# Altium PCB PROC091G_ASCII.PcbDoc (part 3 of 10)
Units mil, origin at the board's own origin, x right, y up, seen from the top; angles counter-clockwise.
Board outline 4538.11 x 994.94 mil, 8 copper layers (Top Layer, GND1, Sig1, PWR1, PWR2, Sig2, GND2, Bottom Layer), stack 59.155 mil thick; 447 components, 329 nets, 5050 pads, 868 vias.
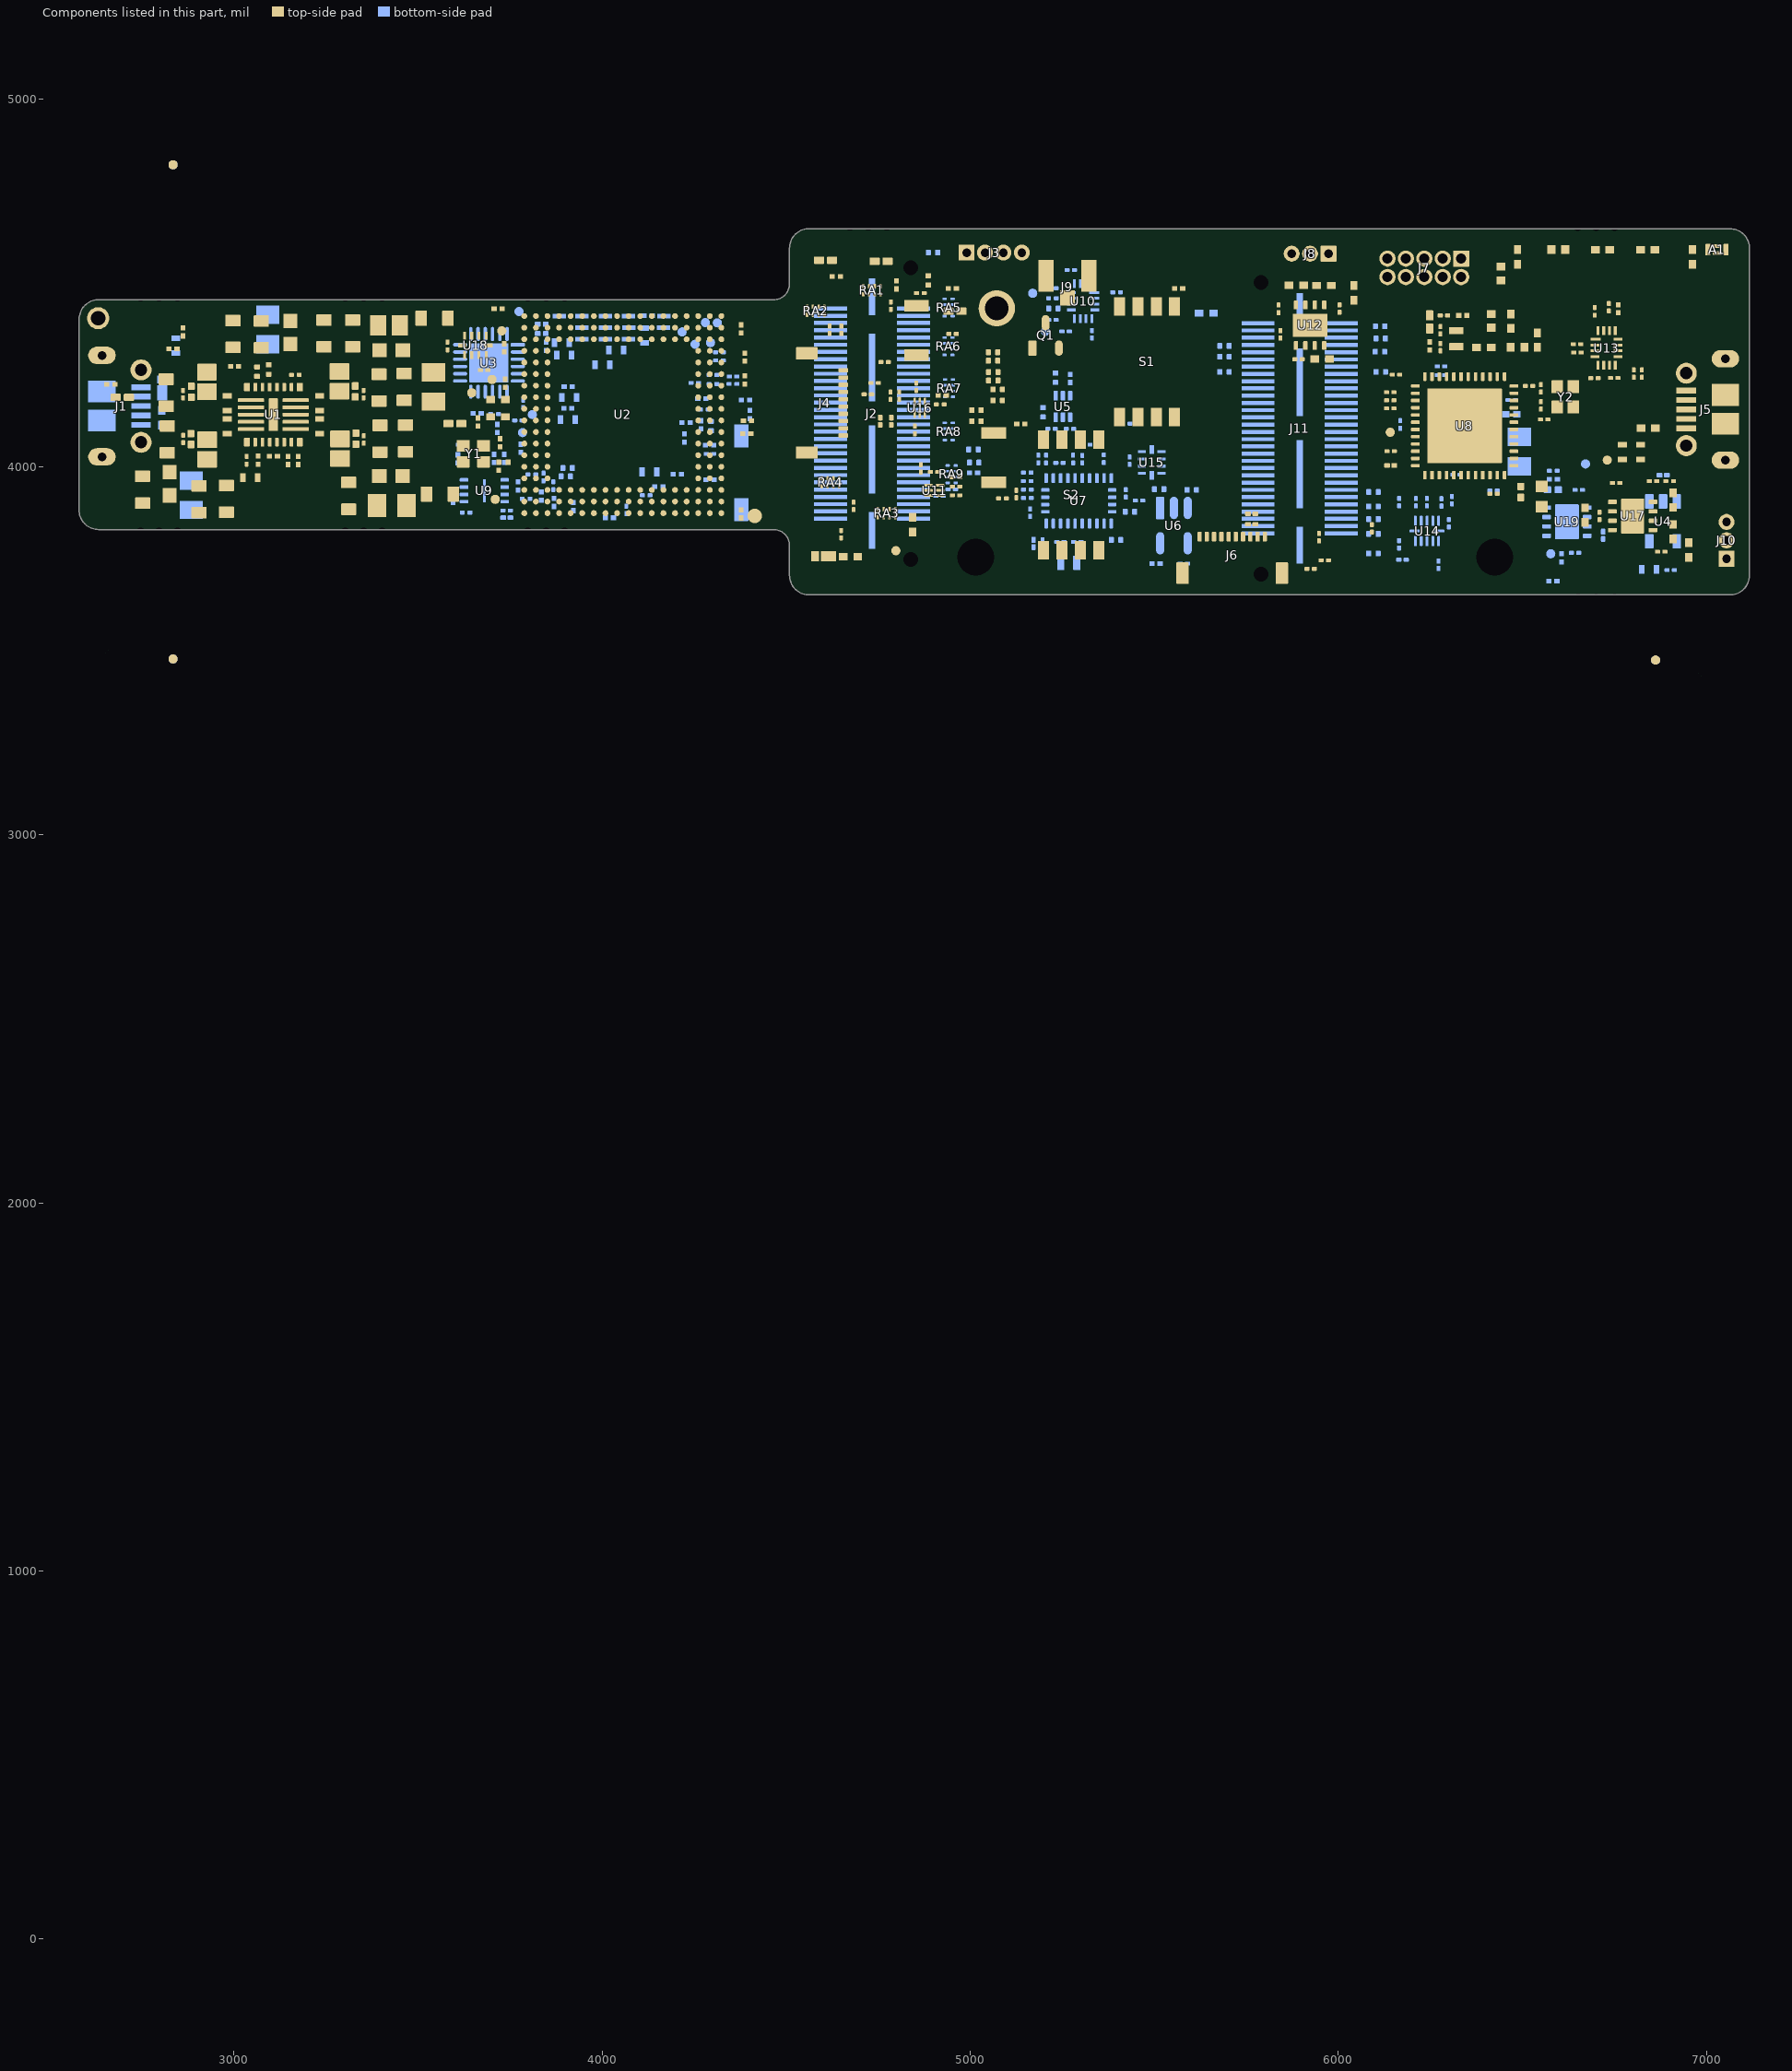
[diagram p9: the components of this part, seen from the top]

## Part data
A1: library part CMP-0087189-1, "RF ANT 2.4GHZ CHIP SOLDER SMD"
C1 C4 C7 C42 C50 C51 C52 C53 C55 C59 C62 C65 C70 C73 C78 C82 C122: library part CMP-0006339-4, "CAP, CERM, 10 uF, 10 V, +/- 20%, X5R, 0402"
C2 C3 C6 C9 C10 C12 C13 C25 C26 C27 C35 C36 C37 C40 C43 C72 C86 C91 C92 C101 C105 C107 C108 C109 C114 C117 C118 C119 C120 C123 C126 C127 C128 C130: library part CMP-0086440-1, "Cap Ceramic 0.1uF 35V X5R 10% Pad SMD 0201 85C T/R"
C5 C11 C15 C16 C24 C100 C115 C116 C129: library part CMP-0086446-1, "1µF ±20% 16V Ceramic Capacitor X5R 0201"
C8 C125: library part CMP-0086445-1, "CAP CER 10000PF 25V X5R 0201"
C14 C71: library part CMP-0080076-1, "CAP, CERM, 4.7 pF, 50 V,+/- 3%, C0G/NP0, 0201"
C17 C18: library part CMP-0086441-1, "Cap Ceramic 8pF 50V C0G 0.1pF SMD 0201 125°C Paper T/R"
C19 C20 C38 C39: library part CMP-0087190-1, "CAP CER 12PF 25V C0G/NP0 0201"
C21 C93: library part CMP-0006345-2, "CAP, CERM, 12 pF, 50 V, +/- 5%, C0G/NP0, 0402"
C22 C23 C41: library part CMP-0085178-1, "CAP, CERM, 1 pF, 50 V,+/- 25%, C0G/NP0, AEC-Q200 Grade 1, 0402"
C28 C29: library part CMP-0089043-3, "CAP CER 22UF 6.3V X5R 0402"
C30 C56 C57 C58 C60 C61 C63 C64 C66 C67 C68 C75 C76 C80 C81 C84 C85 C87 C88 C94 C95 C96 C97 C98: library part CMP-0009781-1, "CAP, CERM, 0.22 uF, 10 V, +/- 20%, X5R, 0201"
C31 C32 C33 C34: library part CMP-0086438-1, "CAP CER 390PF 25V C0G/NP0 0201"
C44 C45 C46 C47 C111 C112 C113 C121 C131 C133 C135 C137 C138 C139 C140 C141: library part CMP-0091983-1, "22µF ±20% 6.3V Ceramic Capacitor X7T 0805 (2012 Metric)"
C69: library part CMP-0009718-2, "CAP, CERM, 0.047 uF, 16 V, +/- 10%, X5R, 0201"
C74 C79 C83 C102 C103: library part CMP-0009657-3, "CAP, CERM, 2.2 uF, 6.3 V, +/- 20%, X5R, 0201"
C89 C90: library part CMP-0081763-1, "CAP, CERM, 1 µF, 6.3 V,+/- 10%, X6S, 0402"
C99 C104: library part CMP-0086306-1, "CAP, CERM, 1.8 pF, 50 V,+/- 6%, C0G/NP0, 0402"
C106 C110: library part CMP-0006692-2, "CAP, CERM, 4700 pF, 50 V, +/- 10%, X7R, 0402"
C124 C132 C134 C136: library part CMP-0008017-1, "CAP, CERM, 10 uF, 10 V, +/- 10%, X7R, 0805"
D1 D2: library part CMP-0028829-2, "Diode, Schottky, 30 V, 2 A, 2-XFDFN"
FID2 FID2_1 FID2_1_1 FID2_1_1_1 FID5_1 FID5_1_1 FID5_1_1_1: library part CMP-0077181-1, "Fiducial mark.  There is nothing to buy or mount."
FL2 FL3 FL4 FL11 FL12 FL14 FL22: library part CMP-0078934-1, "Inductor, Ferrite Bead, Ferrite, 2.2 A, 0.035 ohm, AEC-Q200 Grade 1, SMD"
J1 J5: library part CMP-0055293-1, "Connector, Receptacle, Micro-USB Type B, R/A, Bottom Mount SMT"
J2 J11: library part CMP-0075524-1, "Receptacle, 0.5 mm, 30x2, Gold, TH"
J3: library part CMP-0087187-1, "CONN HDR 1.27MM R/A AU 4POS"
J4 J6: library part CMP-0086453-1, "Easy-On™ Type FFC/FPC Connector, Right-Angle, Surface Mount, ZIF, Bottom Contact Style, 1.10mm Mated Height, 10 Circuits"
J7: library part CMP-0087786-1, "CONN HEADER R/A 10POS 1.27MM"
J8 J10: library part CMP-0087785-1, "CONN HEADER R/A 3POS 1.27MM"
J9: library part CMP-0075320-1, "Receptacle, Ultra Miniature Coaxial, Male Pin, 50 ohm, SMT"
L1 L6: library part CMP-0058626-1, "Inductor, Multilayer, Air Core, 2.4 nH, 0.3 A, 0.15 ohm, SMD"
L2 L3 L4 L5: library part CMP-0087178-1, "FIXED IND 470NH 4.5A 39 MOHM SMD"
L7: library part CMP-0062727-1, "Inductor, Multilayer, Ferrite, 6.8 uH, 0.11 A, 0.25 ohm, SMD"
L8: library part CMP-0003349-2, "Ferrite Bead, 1500 ohm @ 100 MHz, 0.5 A, 0603"
L9 L10: library part CMP-0058624-1, "Inductor, Multilayer, Air Core, 2 nH, 0.3 A, 0.1 ohm, SMD"
L11 L12 L13 L14: library part CMP-0077879-1, "Ferrite Bead, 120 ohm @ 100 MHz, 1.9 A, 0603"
L15: library part CMP-0003363-1, "Ferrite Bead, 220 ohm @ 100 MHz, 2 A, 0805"
LD1 LD2 LD3 LD4 LD5 LD6: library part CMP-0067682-2, "LED, Green, SMD"
Q1: library part CMP-0087176-1, "MOSFET N-CH 100V 170MA SOT23-3"
R1 R3 R7 R8 R18 R19 R20 R21 R22 R23 R35 R36 R43 R44 R45 R59 R65 R77 R78 R80 R81 R82 R83 R84 R85 R93 R94 R95 R96 R98 R104 R110 R118 R122 R124 R125 R134 R177 R178: library part CMP-0088002-1, "10 kOhms ±0.5% 0.05W, 1/20W Chip Resistor 0201 (0603 Metric)  Thin Film"
R2 R12 R14 R28 R30 R31 R32 R41 R51 R57 R58 R60 R61 R62 R66 R67 R68 R70 R71 R72 R73 R74 R76 R86 R87 R90 R91 R97 R99 R100 R101 R102 R103 R105 R106 R109 R112 R113 R115 R116 R120 R121 R123 R127 R128 R129 R131 R136 R139 R142 R143 R144 R145 R146 R147 R148 R149 R150 R151 R152 R153 R154 R155 R157 R160 R161 R166 R168 R182 R183 R184 R185 R186 R187 R188 R189 R190: library part CMP-0086442-2, "RES SMD 0 OHM JUMPER 1/20W 0201"
R4 R5 R9 R29 R37 R89 R92: library part CMP-0027261-3, "RES, 100 k, 1%, 0.05 W, 0201"
R6 R46 R47 R48 R49: library part CMP-0027275-3, "RES, 33.2, 1%, 0.05 W, 0201"
R10 R11 R88 R130 R132 R133 R135 R137 R138 R140: library part CMP-0087185-1, "RES SMD 20 OHM 1% 1/20W 0201"
R13 R15 R17 R42 R111: library part CMP-0027072-1, "RES, 220, 5%, 0.05 W, 0201"
R16 R174 R176: library part CMP-0027880-1, "RES, 7.87 k, 1%, 0.05 W, 0201"
R24: library part CMP-0087183-1, "RES SMD 200 OHM 1% 1/5W 0402"
R25 R26 R33 R34 R38 R40 R64 R69 R141: library part CMP-0027745-1, "RES, 4.99 k, 1%, 0.05 W, 0201"
R27 R39 R107 R108: library part CMP-0027137-1, "RES, 510, 5%, 0.05 W, 0201"
R50 R75: library part CMP-0027052-1, "RES, 1.0 k, 5%, 0.05 W, 0201"
R52: library part CMP-0027452-1, "RES, 1.96 k, 1%, 0.05 W, 0201"
R53 R54 R55 R56: library part CMP-0086444-2, "RES Thick Film SMD 3.83O 1% 1/16W 0402 200ppm/°C"
R79 R180 R181: library part CMP-0087184-1, "RESISTOR, 0201, 0.05W, 1%, 4K7"
R114 R117 R119 R126: library part CMP-0026491-2, "RES, 61.9, 1%, 0.063 W, AEC-Q200 Grade 0, 0402"
R158 R170 R172: library part CMP-0027891-1, "RES, 82.5 k, 1%, 0.05 W, 0201"
R159 R171: library part CMP-0027165-1, "RES, 750, 5%, 0.05 W, 0201"
RA1 RA2 RA3 RA4 RA5 RA6 RA7 RA8 RA9: library part CMP-0087186-1, "RES ARRAY 4 RES ZERO OHM 0502"
S1 S2: library part CMP-0002128-2, "Switch, Slide, SPST 4 poles, SMT"
S3: library part CMP-0087181-1, "SWITCH SLIDE DIP SPST 100MA 6V"
SW2 SW3: library part CMP-0002150-2, "SWITCH TACTILE SPST-NO 0.05A 12V"
TP2 TP3 TP4 TP5 TP6 TP7 TP8 TP9 TP10 TP12 TP13 TP14 TP15 TP16 TP17 TP18 TP19 TP26 TP27 TP46: library part CMP-0078143-3, "TEST POINT.  No entry in BOM."
TP11: library part CMP-0003825-1, "1mm Test Point, SMT"
TP20: library part CMP-0086474-1, "PC Test Point, Loop Brass, Tin Plating 0.047\" (1.19mm) Hole Diameter Mounting Type"
U1: library part CMP-0079120-2, "4-A + 2.5-A + Two 1.5-A Buck Converters With Integrated Switches, RNF0026C (VQFN-HR-26)"
U2: library part CMP-0860942-2, "XI6843ARQGALP, ALP0180A (BGA-180)"
U3: library part CMP-0087172-1, "I/O Controller Interface IC USB to Dual UART bridge"
U4: library part CMP-0035419-1, "Single Output High PSRR LDO, 200 mA, Fixed 3 V Output, 2.7 to 5.5 V Input, 5-pin SOT-23 (DBV), -40 to 85 degC, Green (RoHS & no Sb/Br)"
U5: library part CMP-0067398-2, "Automotive Grade, 1.4V-Capable +/-0.5degC Temperature Sensor with Alert Function and I2C/SMBus, DRL0006A (SOT-OTHER-6)"
U6: library part CMP-0087170-1, "8KB I2C SER EEPROM TSOT 23"
U7: library part CMP-0087171-1, "IMU ACCEL/GYRO/MAG I2C 32BIT"
U8: library part CMP-0083675-2, "SimpleLink(TM) Bluetooth(R) 5 low energy Wireless MCU, RGZ0048A (VQFN-48)"
U9: library part CMP-0078466-1, "ULTRA LOW POWER, 16M-BIT [x 1/x 2/x 4] CMOS MXSMIO (SERIAL MULTI I/O) FLASH MEMORY, SON-8"
U10: library part CMP-0043349-1, "Low-Voltage 8-Bit I2C and SMBus I/O Expander, 1.65 to 5.5 V, -40 to 85 degC, 16-pin UQFN (RSV), Green (RoHS & no Sb/Br)"
U11: library part CMP-0050992-5, "1-Channel, 2:1 Analog Switch, DSF0006A (X2SON-6)"
U12 U17: library part CMP-0065183-3, "Automotive Fault Protected CAN Transceiver With Flexible Data-Rate, DRB0008F (VSON-8)"
U13: library part CMP-0067415-1, "10-Ohm Quad SPDT Analog Switch, RSV0016A (UQFN-16)"
U14: library part CMP-0860038-1, "Automotive 4-Bit Bidirectional Voltage-Level Translator with Auto Direction Sensing and +/-15kV ESD, RUT0012A (UQFN-12)"
U15 U18: library part CMP-0074545-1, "Dual 10-ohm SPDT Analog Switch, RSE0010A (UQFN-10)"
U16: library part CMP-0087998-2, "AND Gate IC 1 Channel  6-SON (1x1)"
U19: library part CMP-0043358-3, "Dual In / Single Out Autoswitching Power Mux, 2.8 to 5.5 V, -40 to 85 degC, 8-pin SON (DRB), Green (RoHS & no Sb/Br)"
Y1: library part CMP-0087164-1, "CRYSTAL 40.0000MHZ 8PF SMD"
Y2: library part CMP-0088076-1, "48MHz ±20ppm Crystal 7pF 50 Ohms 4-SMD, No Lead"
Y3 Y4: library part CMP-0088006-1, "CRYSTAL 32.768KHZ 4PF SMD"
ZZ1: library part CMP-0003616-3
ZZ2: library part CMP-0077236-1
ZZ3: library part CMP-0077237-1
ZZ4 ZZ5.2: library part CMP-0077238-1
ZZ5.1: library part CMP-0077238-1, "Cut the thermal pad(Part Number#GPVOUS-0.125-AC-0816) for the shape and size of the inner surface of the heatsink(Part Number#160018120021) and paste it on the inner surface of the heatsink;"

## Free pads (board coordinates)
  round 10 on Mech21: 1(2782.06,-196.61) 1(2782.06,-196.61) 1(2782.06,5103.39) 1(2782.06,5103.39) 1(3777.02,724.44) 1(3780.02,811.44) 1(3807.02,724.44) 1(3810.02,811.44) 1(3837.02,724.44) 1(3840.02,811.44) 1(3867.02,724.44) 1(3870.02,811.44) 1(3897.02,724.44) 1(3924.02,724.44) 1(3951.02,723.44) 1(3978.02,723.44) 1(3984.02,844.44) 1(3984.02,794.44) 1(3984.02,819.44) 1(4001.02,748.44) 1(4009.02,794.44) 1(4044.47,936.91) 1(4163.02,793.44) 1(4188.02,793.44) 1(4188.02,818.44) 1(4188.02,843.44) 1(4267.02,765.44) 1(4289.02,830.44) 1(4291.02,744.44) 1(4319.02,830.44) 1(4321.02,744.44) 1(4349.02,830.44) 1(4351.02,743.44) 1(4379.02,830.44) 1(4381.02,744.44) 1(4409.02,830.44) 1(4411.02,744.44) 1(4436.02,830.44) 1(4438.02,744.44) 1(5496.22,2885.93) 1(5496.22,3279.63) 1(5501.22,3560.93) 1(5501.22,3954.63) 1(5529.55,-196.61) 1(5529.55,-196.61) 1(5529.55,5103.39) 1(5529.55,5103.39)
  round 7.87 on Mech21: 1(2823.43,27.44) 1(2823.43,27.44) 1(2823.43,137.44) 1(2823.43,137.44) 1(2823.43,225.19) 1(2823.43,225.19) 1(2823.43,335.19) 1(2823.43,335.19) 1(2823.43,425.05) 1(2823.43,425.05) 1(2823.43,535.05) 1(2823.43,535.05) 1(2887.5,965.95) 1(2887.5,1804.93) 1(2887.5,1078.77) 1(2887.5,1692.11) 1(2951.28,965.95) 1(2951.28,1804.93) 1(3029.52,27.44) 1(3029.52,27.44) 1(3029.52,137.44) 1(3029.52,137.44) 1(3029.52,225.19) 1(3029.52,225.19) 1(3029.52,335.19) 1(3029.52,335.19) 1(3029.52,425.05) 1(3029.52,425.05) 1(3029.52,535.05) 1(3029.52,535.05) 1(3147.42,2384.48) 1(3147.42,2384.48) 1(3147.42,3223.46) 1(3147.42,3223.46) 1(3147.42,2497.3) 1(3147.42,3110.64) 1(3172.54,1078.77) 1(3172.54,1692.11) 1(3172.54,965.95) 1(3172.54,965.95) 1(3172.54,1804.93) 1(3172.54,1804.93) 1(3217.09,-97.78) 1(3217.09,-97.78) 1(3217.09,-7.23) 1(3272.21,-97.78) 1(3272.21,-97.78) 1(3272.21,-7.23) 1(3286.09,-98.78) 1(3286.09,-98.78) 1(3286.09,-8.23) 1(3318.31,815.96) 1(3318.31,858.28) 1(3324.65,3810.58) 1(3324.65,3810.58) 1(3324.65,3837.33) 1(3324.65,4451.33) 1(3324.65,4478.08) 1(3324.65,4478.08) 1(3341.21,-98.78) 1(3341.21,-98.78) 1(3341.21,-8.23) 1(3351.09,-100.24) 1(3351.09,-100.24) 1(3351.09,-9.69) 1(3368.68,2384.48) 1(3368.68,3223.46) 1(3384.65,3750.58) 1(3384.65,3750.58) 1(3384.65,4538.08) 1(3384.65,4538.08) 1(3389.98,1572.42) 1(3389.98,1655.09) 1(3406.21,-100.24) 1(3406.21,-100.24) 1(3406.21,-9.69) 1(3418.15,1040.47) 1(3418.15,1048.34) 1(3418.15,1168.42) 1(3418.15,1176.3) 1(3418.15,1040.47) 1(3418.15,1176.3) 1(3421.09,-100.24) 1(3421.09,-100.24) 1(3421.09,-9.69) 1(3427.99,1040.47) 1(3427.99,1176.3) 1(3432.46,2497.3) 1(3432.46,3110.64) 1(3432.46,2384.48) 1(3432.46,3223.46) 1(3438.39,815.96) 1(3438.39,898.64) 1(3455.06,1252.84) 1(3455.06,1252.84) 1(3455.06,1339.46) 1(3455.06,1435.43) 1(3455.06,1522.04) 1(3455.06,1522.04) 1(3462.15,3750.58) 1(3462.15,3750.58) 1(3462.15,4538.08) 1(3462.15,4538.08) 1(3471.69,669.79) 1(3471.69,669.79) 1(3471.69,756.4) 1(3471.69,852.37) 1(3471.69,938.99) 1(3471.69,938.99) 1(3476.21,-100.24) 1(3476.21,-100.24) 1(3476.21,-9.69) 1(3491.09,-100.24) 1(3491.09,-100.24) 1(3491.09,-9.69) 1(3510.06,1612.77) 1(3510.06,1655.09) 1(3517.56,1040.47) 1(3523.91,2372.83) 1(3523.91,2372.83) 1(3523.91,2376.33) 1(3523.91,2376.33) 1(3523.91,2448.33) 1(3523.91,2448.33) 1(3523.91,2451.83) 1(3523.91,2451.83) 1(3536.41,2363.33) 1(3536.41,2363.33) 1(3536.41,2461.33) 1(3536.41,2461.33) 1(3544.13,1176.3) 1(3546.21,-100.24) 1(3546.21,-100.24) 1(3546.21,-9.69) 1(3553.97,1040.47) 1(3553.97,1040.47) 1(3553.97,1048.34) 1(3553.97,1176.3) 1(3553.97,1168.42) 1(3553.97,1176.3) 1(3559.65,3750.58) 1(3559.65,4538.08) 1(3559.65,3750.58) 1(3559.65,3837.33) 1(3559.65,4451.33) 1(3559.65,4538.08) 1(3561.09,-98.78) 1(3561.09,-98.78) 1(3561.09,-8.23) 1(3584.98,1252.84) 1(3584.98,1252.84) 1(3584.98,1339.46) 1(3584.98,1435.43) 1(3584.98,1522.04) 1(3584.98,1522.04) 1(3594.02,1269.94) 1(3594.02,1269.94) 1(3594.02,1347.44) 1(3594.02,1347.44) 1(3594.02,1367.44) 1(3594.02,1367.44) 1(3594.02,1447.44) 1(3594.02,1447.44) 1(3594.02,1467.44) 1(3594.02,1467.44) 1(3594.02,1544.94) 1(3594.02,1544.94) 1(3601.61,669.79) 1(3601.61,669.79) 1(3601.61,756.4) 1(3601.61,852.37) 1(3601.61,938.99) 1(3601.61,938.99) 1(3603.52,1257.44) 1(3603.52,1257.44) 1(3603.52,1557.44) 1(3603.52,1557.44) 1(3604.02,1357.44) 1(3604.02,1357.44) 1(3604.02,1457.44) 1(3604.02,1457.44) 1(3607.02,1257.44) 1(3607.02,1257.44) 1(3607.02,1557.44) 1(3613.91,2363.33) 1(3613.91,2363.33) 1(3613.91,2461.33) 1(3613.91,2461.33) 1(3614.28,1031.89) 1(3614.28,1031.89) 1(3614.28,1246.39) 1(3614.28,1246.39) 1(3616.21,-98.78) 1(3616.21,-98.78) 1(3616.21,-8.23) 1(3623.91,2373.33) 1(3623.91,2373.33) 1(3623.91,2451.33) 1(3623.91,2451.33) 1(3627.65,676.89) 1(3627.65,676.89) 1(3627.65,754.39) 1(3627.65,754.39) 1(3627.65,774.39) 1(3627.65,774.39) 1(3627.65,854.39) 1(3627.65,854.39) 1(3627.65,874.39) 1(3627.65,874.39) 1(3627.65,951.89) 1(3627.65,951.89) 1(3633.91,2363.33) 1(3633.91,2363.33) 1(3633.91,2461.33) 1(3633.91,2461.33) 1(3636.09,-100.24) 1(3636.09,-100.24) 1(3636.09,-9.69) 1(3637.15,664.39) 1(3637.15,664.39) 1(3637.15,964.39) 1(3637.15,964.39) 1(3637.65,764.39) 1(3637.65,764.39) 1(3637.65,864.39) 1(3637.65,864.39) 1(3640.65,664.39) 1(3640.65,664.39) 1(3640.65,964.39) 1(3679.02,1257.44) 1(3679.02,1257.44) 1(3679.02,1557.44) 1(3682.02,1357.44) 1(3682.02,1357.44) 1(3682.02,1457.44) 1(3682.02,1457.44) 1(3682.52,1257.44) 1(3682.52,1257.44) 1(3682.52,1557.44) 1(3682.52,1557.44) 1(3691.21,-100.24) 1(3691.21,-100.24) 1(3691.21,-9.69) 1(3692.02,1269.94) 1(3692.02,1269.94) 1(3692.02,1347.44) 1(3692.02,1347.44) 1(3692.02,1367.44) 1(3692.02,1367.44) 1(3692.02,1447.44) 1(3692.02,1447.44) 1(3692.02,1467.44) 1(3692.02,1467.44) 1(3692.02,1544.94) 1(3692.02,1544.94) 1(3706.99,2543.35) 1(3706.99,2663.42) 1(3712.65,664.39) 1(3712.65,664.39) 1(3712.65,964.39) 1(3713.91,2363.33) 1(3713.91,2363.33) 1(3713.91,2461.33) 1(3713.91,2461.33) 1(3715.65,764.39) 1(3715.65,764.39) 1(3715.65,864.39) 1(3715.65,864.39) 1(3716.09,-96.97) 1(3716.09,-96.97) 1(3716.09,-6.42) 1(3716.15,664.39) 1(3716.15,664.39) 1(3716.15,964.39) 1(3716.15,964.39) 1(3723.91,2373.33) 1(3723.91,2373.33) 1(3723.91,2451.33) 1(3723.91,2451.33) 1(3724.28,1031.89) 1(3724.28,1031.89) 1(3724.28,1246.39) 1(3724.28,1246.39) 1(3725.65,676.89) 1(3725.65,676.89) 1(3725.65,754.39) 1(3725.65,754.39) 1(3725.65,774.39) 1(3725.65,774.39) 1(3725.65,854.39) 1(3725.65,854.39) 1(3725.65,874.39) 1(3725.65,874.39) 1(3725.65,951.89) 1(3725.65,951.89) 1(3733.91,2363.33) 1(3733.91,2363.33) 1(3733.91,2461.33) 1(3733.91,2461.33) 1(3749.32,2663.42) 1(3771.21,-96.97) 1(3771.21,-96.97) 1(3771.21,-6.42) 1(3789.67,2543.35) 1(3811.41,2363.33) 1(3811.41,2363.33) 1(3811.41,2461.33) 1(3811.41,2461.33) 1(3823.91,2372.83) 1(3823.91,2372.83) 1(3823.91,2376.33) 1(3823.91,2448.33) 1(3823.91,2451.83) 1(3823.91,2451.83) 1(3839.29,1436.2) 1(3839.29,1530.69) 1(3849.14,1436.2) 1(3849.14,1530.69) 1(3888.51,1436.2) 1(3912.13,1530.69) 1(3921.97,1436.2) 1(3921.97,1530.69) 1(3923.02,2908.02) 1(3923.02,2908.02) 1(3923.02,3242.66) 1(3923.02,3242.66) 1(3994.61,1526.09) 1(4038.1,2440.47) 1(4038.1,2448.35) 1(4038.1,2440.47) 1(4038.1,2568.42) 1(4038.1,2576.3) 1(4038.1,2576.3) 1(4047.94,2440.47) 1(4066.93,2016.12) 1(4069.15,1542.59) 1(4069.15,1739.44) 1(4071.85,2100.76) 1(4074.51,2576.3) 1(4079.73,2100.76) 1(4086.62,2016.12) 1(4089.1,1329.24) 1(4140.02,1739.44) 1(4159.96,1329.24) 1(4159.96,1526.09) 1(4164.08,2440.47) 1(4164.08,2576.3) 1(4168.31,2016.12) 1(4168.31,2100.76) 1(4168.81,2190.61) 1(4173.15,1851.31) 1(4173.73,2275.26) 1(4173.92,2440.47) 1(4173.92,2576.3) 1(4173.92,2440.47) 1(4173.92,2448.35) 1(4173.92,2568.42) 1(4173.92,2576.3) 1(4176.18,2016.12) 1(4176.18,2100.76) 1(4178.07,1935.95) 1(4181.6,2275.26) 1(4185.95,1935.95) 1(4188.49,2190.61) 1(4192.84,1851.31) 1(4226.63,1542.59) 1(4228.62,2329.44) 1(4233.54,2414.09) 1(4241.41,2414.09) 1(4248.3,2329.44) 1(4257.66,2908.02) 1(4257.66,2908.02) 1(4257.66,3242.66) 1(4257.66,3242.66) 1(4270.18,2190.61) 1(4270.18,2275.26) 1(4274.53,1851.31) 1(4274.53,1935.95) 1(4278.06,2190.61) 1(4278.06,2275.26) 1(4282.4,1851.31) 1(4282.4,1935.95) 1(4321.32,1868.39) 1(4321.32,1907.76) 1(4329.99,2329.44) 1(4329.99,2414.09) 1(4337.87,2329.44) 1(4337.87,2414.09) 1(4396.13,1868.39) 1(4396.13,1923.51) 1(4507.31,2354.05) 1(4507.31,2476.1) 1(4565.61,1217.83) 1(4565.61,1339.88) 1(4578.18,2476.1) 1(4594.02,3254.94) 1(4594.02,3254.94) 1(4594.02,3332.44) 1(4594.02,3332.44) 1(4594.02,3352.44) 1(4594.02,3352.44) 1(4594.02,3432.44) 1(4594.02,3432.44) 1(4594.02,3452.44) 1(4594.02,3452.44) 1(4594.02,3529.94) 1(4594.02,3529.94) 1(4603.52,3242.44) 1(4603.52,3242.44) 1(4603.52,3542.44) 1(4603.52,3542.44) 1(4604.02,3342.44) 1(4604.02,3342.44) 1(4604.02,3442.44) 1(4604.02,3442.44) 1(4607.02,3242.44) 1(4607.02,3542.44) 1(4607.02,3542.44) 1(4616.15,3750.58) 1(4616.15,3837.33) 1(4616.15,4451.33) 1(4616.15,4538.08) 1(4616.15,3750.58) 1(4616.15,4538.08) 1(4636.48,1339.88) 1(4647.07,2354.05) 1(4679.02,3242.44) 1(4679.02,3542.44) 1(4679.02,3542.44) 1(4682.02,3342.44) 1(4682.02,3342.44) 1(4682.02,3442.44) 1(4682.02,3442.44) 1(4682.52,3242.44) 1(4682.52,3242.44) 1(4682.52,3542.44) 1(4682.52,3542.44) 1(4692.02,3254.94) 1(4692.02,3254.94) 1(4692.02,3332.44) 1(4692.02,3332.44) 1(4692.02,3352.44) 1(4692.02,3352.44) 1(4692.02,3432.44) 1(4692.02,3432.44) 1(4692.02,3452.44) 1(4692.02,3452.44) 1(4692.02,3529.94) 1(4692.02,3529.94) 1(4705.38,1217.83) 1(4713.65,3750.58) 1(4713.65,3750.58) 1(4713.65,4538.08) 1(4713.65,4538.08) 1(4734.02,373.44) 1(4734.02,373.44) 1(4734.02,587.94) 1(4734.02,587.94) 1(4791.15,3750.58) 1(4791.15,3750.58) 1(4791.15,4538.08) 1(4791.15,4538.08) 1(4844.02,373.44) 1(4844.02,373.44) 1(4844.02,587.94) 1(4844.02,587.94) 1(4851.15,3810.58) 1(4851.15,3810.58) 1(4851.15,3837.33) 1(4851.15,4451.33) 1(4851.15,4478.08) 1(4851.15,4478.08) 1(4856.02,373.44) 1(4856.02,373.44) 1(4856.02,587.94) 1(4856.02,587.94) 1(4966.02,373.44) 1(4966.02,373.44) 1(4966.02,587.94) 1(4966.02,587.94) 1(4979.06,1852.98) 1(4979.06,1992.74) 1(5015.31,358.32) 1(5015.31,358.32) 1(5015.31,444.93) 1(5015.31,540.9) 1(5015.31,627.52) 1(5015.31,627.52) 1(5101.1,1921.88) 1(5101.1,1992.74) 1(5134.02,1794.94) 1(5134.02,1794.94) 1(5134.02,1872.44) 1(5134.02,1872.44) 1(5134.02,1892.44) 1(5134.02,1892.44) 1(5134.02,1972.44) 1(5134.02,1972.44) 1(5134.02,1992.44) 1(5134.02,1992.44) 1(5134.02,2069.94) 1(5134.02,2069.94) 1(5135.21,2222.28) 1(5143.09,2222.28) 1(5143.52,1782.44) 1(5143.52,1782.44) 1(5143.52,2082.44) 1(5143.52,2082.44) 1(5144.02,1882.44) 1(5144.02,1882.44) 1(5144.02,1982.44) 1(5144.02,1982.44) 1(5145.23,358.32) 1(5145.23,358.32) 1(5145.23,444.93) 1(5145.23,540.9) 1(5145.23,627.52) 1(5145.23,627.52) 1(5147.02,1782.44) 1(5147.02,2082.44) 1(5147.02,2082.44) 1(5204.83,60.24) 1(5204.83,60.24) 1(5204.83,115.35) 1(5204.83,355.51) 1(5204.83,414.57) 1(5204.83,414.57) 1(5218.07,3107.32) 1(5219.02,1782.44) 1(5219.02,2082.44) 1(5219.02,2082.44) 1(5222.02,1882.44) 1(5222.02,1882.44) 1(5222.02,1982.44) 1(5222.02,1982.44) 1(5222.52,1782.44) 1(5222.52,1782.44) 1(5222.52,2082.44) 1(5222.52,2082.44) 1(5229.88,3040.39) 1(5232.02,1794.94) 1(5232.02,1794.94) 1(5232.02,1872.44) 1(5232.02,1872.44) 1(5232.02,1892.44) 1(5232.02,1892.44) 1(5232.02,1972.44) 1(5232.02,1972.44) 1(5232.02,1992.44) 1(5232.02,1992.44) 1(5232.02,2069.94) 1(5232.02,2069.94) 1(5234.79,641.69) 1(5234.79,641.69) 1(5234.79,1055.08) 1(5234.79,1055.08) 1(5234.79,1086.69) 1(5234.79,1086.69) 1(5234.79,1500.08) 1(5234.79,1500.08) 1(5240.26,60.24) 1(5240.26,60.24) 1(5240.26,414.57) 1(5240.26,414.57) 1(5245.63,3040.39) 1(5245.63,3107.32) 1(5248.14,414.57) 1(5276.52,1539.33) 1(5276.52,1657.44) 1(5296.21,1539.33) 1(5296.21,1539.33) 1(5296.21,1570.83) 1(5296.21,1625.94) 1(5296.21,1657.44) 1(5296.21,1657.44) 1(5331.83,4040.88) 1(5331.83,4096) 1(5346.52,4219.33) 1(5346.52,4337.44) 1(5366.21,4219.33) 1(5366.21,4219.33) 1(5366.21,4250.83) 1(5366.21,4305.94) 1(5366.21,4337.44) 1(5366.21,4337.44) 1(5376.48,1570.83) 1(5376.48,1570.83) 1(5376.48,1625.94) 1(5376.48,1625.94) 1(5393.21,1670.28) 1(5394.83,4424.76) 1(5394.83,4472.01) 1(5401.09,1670.28) 1(5422.38,4040.88) 1(5422.38,4040.88) 1(5422.38,4096) 1(5422.38,4096) 1(5431.09,4210) 1(5431.09,4300.55) 1(5431.09,4300.55) 1(5448.92,414.57) 1(5467.03,1570.83) 1(5467.03,1625.94) 1(5486.21,4210) 1(5486.21,4300.55) 1(5486.21,4300.55) 1(5510.38,641.69) 1(5510.38,641.69) 1(5510.38,1055.08) 1(5510.38,1055.08) 1(5510.38,1086.69) 1(5510.38,1086.69) 1(5510.38,1500.08) 1(5510.38,1500.08) 1(5633.96,60.24) 1(5633.96,60.24) 1(5633.96,414.57) 1(5633.96,414.57) 1(5673.33,60.24) 1(5673.33,60.24) 1(5673.33,414.57) 1(5673.33,414.57) 1(5732.39,60.24) 1(5732.39,60.24) 1(5732.39,414.57) 1(5732.39,414.57) 1(5771.76,60.24) 1(5771.76,60.24) 1(5771.76,414.57) 1(5771.76,414.57)
  round 12.2 on Mech21: 1(2858.69,1057.92) 1(2863.69,1187.92) 1(2863.69,1237.92) 1(2863.86,1139.38) 1(2887.33,603.84) 1(2887.5,688.67) 1(2889.02,2149.44) 1(2904.02,3246.44) 1(2905.02,2848.44) 1(2907.02,2007.44) 1(2907.07,3145.39) 1(2909.02,2546.44) 1(2911.02,2743.44) 1(2913.02,3072.44) 1(2913.02,3107.44) 1(2914.02,2893.44) 1(2922.02,2648.44) 1(2927.02,1911.44) 1(2930.02,2167.44) 1(2956.02,2089.44) 1(2960.02,2134.44) 1(2965.02,786.44) 1(2967.02,3114.44) 1(2976.02,1916.44) 1(2979,1651.19) 1(2980.33,3280.76) 1(2981.02,2895.44) 1(2984.63,1096.92) 1(2986.27,1170.92) 1(2992.27,1214.92) 1(2996.27,1244.92) 1(2996.53,1142.18) 1(3007.02,2094.44) 1(3008.33,603.84) 1(3008.5,688.67) 1(3009.02,2246.44) 1(3009.02,3080.44) 1(3011.02,2991.44) 1(3012.02,3446.44) 1(3020.02,2722.44) 1(3020.33,787.09) 1(3027.02,2604.44) 1(3029.02,2506.44) 1(3030.02,1134.17) 1(3030.02,1368.66) 1(3030.02,1618.66) 1(3030.02,1768.66) 1(3041.02,2884.44) 1(3047.02,2684.44) 1(3051.02,3008.44) 1(3058.66,2609.11) 1(3062.02,2908.44) 1(3063.02,1477.44) 1(3063.02,1513.44) 1(3066.02,1580.44) 1(3070.02,1219.44) 1(3071.02,1433.09) 1(3071.02,2784.44) 1(3071.27,1080.92) 1(3072.02,1621.44) 1(3072.02,1668.44) 1(3072.27,1127.92) 1(3074.02,2584.44) 1(3078.02,1547.44) 1(3079.27,1161.92) 1(3090.83,738.34) 1(3092.02,2708.44) 1(3097.48,2808.44) 1(3098.02,2488.44) 1(3098.02,3084.44) 1(3139.61,596.21) 1(3139.77,681.05) 1(3153.02,1772.9) 1(3158.02,1731.44) 1(3164.27,1037.92) 1(3173.02,592.44) 1(3184.02,1936.44) 1(3186.02,2027.44) 1(3187.02,1900.44) 1(3195.02,1975.44) 1(3203.27,1078.92) 1(3205.27,1127.92) 1(3207.02,4227.18) 1(3209.49,-68.3) 1(3220.02,954.44) 1(3228.24,745.93) 1(3229.02,4051.43) 1(3229.02,4079.73) 1(3235.02,1693.44) 1(3235.02,1736.44) 1(3240.65,2863.39) 1(3241.02,1837.44) 1(3241.65,2907.39) 1(3241.65,2945.39) 1(3242.02,2546.44) 1(3242.02,2618.44) 1(3242.02,2668.44) 1(3242.02,2741.44) 1(3242.17,2577.59) 1(3242.37,3010.66) 1(3243.02,3045.44) 1(3244.65,-110.46) 1(3244.65,17.54) 1(3245.2,2813.81) 1(3245.98,4258.58) 1(3246.02,2511.44) 1(3246.11,2782.44) 1(3248.02,3080.44) 1(3253.02,2709.44) 1(3253.02,4108.98) 1(3253.02,4140.38) 1(3257.02,1883.44) 1(3258.02,2199.44) 1(3265.02,1743.44) 1(3266.02,2048.44) 1(3271.02,4280.44) 1(3273.02,2092.44) 1(3278.02,2347.44) 1(3283.02,4552.44) 1(3285.27,-99.08) 1(3286.02,1974.44) 1(3287.47,1942.98) 1(3288.02,1796.44) 1(3288.02,1872.44) 1(3289.02,3201.98) 1(3289.94,2407.09) 1(3289.94,2803.96) 1(3296.28,2322.39) 1(3296.91,2277.33) 1(3298.91,2230.33) 1(3303.02,927.44) 1(3303.02,2122.44) 1(3303.02,2172.44) 1(3303.58,707.61) 1(3307.44,891.75) 1(3312.83,783.48) 1(3313.02,652.44) 1(3313.02,2042.44) 1(3313.02,2072.44) 1(3313.65,-115.46) 1(3313.65,16.54) 1(3317.51,1885.94) 1(3319.02,2586.44) 1(3323.02,2812.44) 1(3323.02,2912.44) 1(3323.76,2695.7) 1(3325.02,2884.44) 1(3325.28,2192.44) 1(3326.02,2984.44) 1(3329.02,2784.44) 1(3330.28,2253.39) 1(3333.02,2122.46) 1(3333.02,2462.44) 1(3338.02,2606.44) 1(3350.82,1987.67) 1(3352.27,745.92) 1(3359.02,1712.44) 1(3359.27,-123.08) 1(3361,1096.71) 1(3361,1146.71) 1(3361,1196.71) 1(3361,1246.71) 1(3361,1296.71) 1(3361,1351.71) 1(3361,1556.71) 1(3361,1451.71) 1(3361,1046.71) 1(3361.02,1631.44) 1(3362.02,1672.44) 1(3362.02,1916.44) 1(3365.02,1394.44) 1(3366.28,4154.39) 1(3367.02,1492.44) 1(3367.02,4095.44) 1(3368.02,1831.44) 1(3371.02,1967.44) 1(3373.02,2007.87) 1(3373.02,2202.44) 1(3373.28,2361.39) 1(3374.02,2073.44) 1(3374.02,4045.44) 1(3374.03,4210.63) 1(3376.02,1799.44) 1(3378.35,850.84) 1(3378.65,15.09) 1(3379.02,1527.44) 1(3382.02,1583.44) 1(3390.04,2132.82) 1(3393.02,1142.44) 1(3393.27,-122.08) 1(3395.27,745.92) 1(3396.28,2233.39) 1(3400.02,4387.44) 1(3401.02,1765.44) 1(3401.02,3308.44) 1(3402.02,1958.44) 1(3403.02,1992.44) 1(3403.02,4252.44) 1(3408.28,2361.39) 1(3409.85,936.49) 1(3411.84,636.35) 1(3413.02,1848.44) 1(3413.02,2202.44) 1(3417.02,1618.44) 1(3420.02,1243.44) 1(3425.02,1323.44) 1(3438.02,1740.44) 1(3441.97,707.61) 1(3443.02,1409.44) 1(3443.02,2202.44) 1(3443.02,3893.44) 1(3443.02,4131.44) 1(3444.28,4160.39) 1(3444.28,4410.39) 1(3447.02,1623.44) 1(3448.65,-114.46) 1(3448.65,15.09) 1(3449.02,665.44) 1(3453.02,772.44) 1(3453.02,1348.44) 1(3453.02,2462.44) 1(3455.02,1241.44) 1(3458.02,1902.44) 1(3458.02,2052.44) 1(3460.02,947.44) 1(3461.02,740.44) 1(3463.02,908.44) 1(3463.02,2392.44) 1(3463.91,2251.33) 1(3466.84,636.35) 1(3467.02,2081.44) 1(3468.65,3016.68) 1(3472.27,815.92) 1(3473.02,2352.44) 1(3473.02,2827.64) 1(3473.02,2859.04) 1(3474.02,1806.37) 1(3474.63,3089.4) 1(3475.02,2591.42) 1(3475.02,2622.82) 1(3478.02,1984.44) 1(3481.02,1719.44) 1(3483.02,2222.44) 1(3483.02,2502.44) 1(3487.03,-111.06) 1(3490.02,1875.44) 1(3490.02,2709.53) 1(3490.02,2740.93) 1(3490.73,2989.46) 1(3494.02,2063.44) 1(3495.02,2886.7) 1(3495.02,2918.1) 1(3495.28,4232.39) 1(3496.28,4334.39) 1(3500.02,1539.44) 1(3501.33,2363.07) 1(3502.28,4201.39) 1(3502.28,4268.39) 1(3502.28,4305.39) 1(3503.02,2532.37) 1(3503.02,2563.77) 1(3503.28,2297.39) 1(3503.91,2092.33) 1(3509.02,1806.44) 1(3510.28,4167.39) 1(3511.27,948.92) 1(3512.02,1729.44) 1(3512.02,1987.44) 1(3513.02,982.44) 1(3518.65,-121.46) 1(3518.65,15.09) 1(3519.02,1898.44) 1(3528.02,2768.59) 1(3528.02,2799.99) 1(3529.02,2175.44) 1(3530.02,2841.44) 1(3531.02,2650.48) 1(3531.02,2681.88) 1(3533.02,1702.44) 1(3539.02,1658.44) 1(3541.91,2240.33) 1(3544.02,3245.44) 1(3548.02,1887.17) 1(3548.27,-98.36) 1(3549.02,1557.44) 1(3553.02,949.44) 1(3553.02,997.44) 1(3563.02,632.44) 1(3566.02,1685.44) 1(3571.02,2009.44) 1(3573.02,1093.44) 1(3573.61,1765.5) 1(3574.02,1922.44) 1(3574.02,2042.44) 1(3574.02,2637.44) 1(3575.02,1870.44) 1(3576.02,1201.44) 1(3577.02,2071.44) 1(3578.02,1827.44) 1(3583.02,1952.44) 1(3583.02,2921.44) 1(3584.02,2505.44) 1(3588.65,-118.71) 1(3588.65,16.54) 1(3604.02,1642.44) 1(3608.02,2684.44) 1(3613.02,2484.44) 1(3613.02,3242.44) 1(3613.52,2932.44) 1(3614.13,2527.06) 1(3615.28,2352.39) 1(3616.02,1918.44) 1(3618.27,-131.08) 1(3619.02,2293.44) 1(3619.93,4226.73) 1(3620.02,3528.44) 1(3620.62,4326.73) 1(3623.02,632.44) 1(3625.02,2253.44) 1(3626.02,1787.44) 1(3627.02,4104.44) 1(3630.02,1660.44) 1(3634.02,2685.44) 1(3638.02,4151.44) 1(3643.02,2992.44) 1(3643.02,3082.44) 1(3644.02,2020.44) 1(3644.02,2503.44) 1(3647.02,4383.44) 1(3650.02,3139.44) 1(3652.02,3174.44) 1(3655.28,4195.39) 1(3656.65,2844.39) 1(3658.02,4330.44) 1(3658.4,2669.8) 1(3660.65,2774.39) 1(3663.02,2139.44) 1(3663.02,2912.44) 1(3663.02,2952.44) 1(3663.65,-117.46) 1(3663.65,15.09) 1(3664.02,1999.44) 1(3665.71,2877.45) 1(3666.28,4250.39) 1(3671.65,3020.39) 1(3677.51,2992.09) 1(3677.9,1751.56) 1(3681.02,3115.44) 1(3681.53,4296.93) 1(3685.65,3047.39) 1(3695.14,-91.95) 1(3699.02,4255.44) 1(3716.02,2619.44) 1(3717.02,2181.44) 1(3718.27,1469.92) 1(3719.13,2293.33) 1(3720.02,2067.44) 1(3730.02,1811.44) 1(3732.27,2683.01) 1(3733.02,642.44) 1(3736.27,1426.92) 1(3743.65,-118.71) 1(3743.65,18.35) 1(3745.65,2755.39) 1(3750.27,1595.92) 1(3750.27,1620.92) 1(3754.02,3244.44) 1(3763.27,1334.92) 1(3763.79,1379.44) 1(3765.65,2722.39) 1(3767.02,3334.44) 1(3775.11,1427.08) 1(3779.27,1268.92) 1(3782.27,-73.08) 1(3782.27,1623.23) 1(3783.02,950.44) 1(3783.27,1596.92) 1(3784.02,917.44) 1(3789.74,993.39) 1(3792.65,3047.39) 1(3797.36,1832.63) 1(3803.02,642.44) 1(3806.65,3182.39) 1(3806.65,3240.39) 1(3808.27,2518.92) 1(3812.65,3074.39) 1(3813.02,3332.44) 1(3815.27,2626.92) 1(3815.65,3123.39) 1(3823.02,1092.44) 1(3823.02,2912.44) 1(3823.02,3262.44) 1(3823.02,3292.44) 1(3823.65,2862.39) 1(3827.65,1311.54) 1(3828.65,2657.39) 1(3832.27,1042.92) 1(3833.57,1608.92) 1(3835.02,1730.44) 1(3836.02,1770.44) 1(3843.02,692.44) 1(3860.27,2512.92) 1(3864.65,1608.54) 1(3869.02,2385.44) 1(3873.02,1092.44) 1(3882.02,669.44) 1(3882.65,3533.39) 1(3883.02,636.44) 1(3892.02,3381.44) 1(3895.02,2509.44) 1(3897.02,2641.44) 1(3897.27,1287.92) 1(3901.33,2772.57) 1(3902.02,2611.44) 1(3906.02,1959.44) 1(3908.02,1781.62) 1(3908.02,1844.44) 1(3912.27,1613.92) 1(3913.02,602.44) 1(3913.65,2721.89) 1(3915.02,668.44) 1(3916.02,635.44) 1(3916.02,2068.44) 1(3918.65,3529.39) 1(3922.27,1330.92) 1(3922.27,1433.92) 1(3924.65,3215.39) 1(3925.02,1687.44) 1(3927.87,3183.61) 1(3928.65,3071.39) 1(3928.65,3144.39) 1(3929.65,3110.39) 1(3930.27,1257.92) 1(3930.65,3033.39) 1(3940.27,1612.92) 1(3944.2,1457.85) 1(3948.65,2990.39) 1(3949.02,1535.44) 1(3950.02,3474.44) 1(3951.02,1492.44) 1(3953.65,2912.39) 1(3954.65,2957.39) 1(3955.65,2607.39) 1(3956.02,1237.44) 1(3958.02,1024.44) 1(3962.02,2011.44) 1(3964.02,1071.44) 1(3964.02,1649.44) 1(3965.79,1379.44) 1(3969.02,2243.15) 1(3970.65,3537.39) 1(3971.74,983.39) 1(3973.27,1340.92) 1(3975.02,938.44) 1(3977.02,2484.44) 1(3978.27,1471.92) 1(3982.27,1244.92) 1(3996.65,2915.39) 1(3999.02,3230.44) 1(4006.02,2484.44) 1(4009.02,3100.44) 1(4010.65,3534.39) 1(4014.02,2598.44) 1(4016.02,1821.44) 1(4019.02,2326.44) 1(4020.02,3209.44) 1(4022.02,2247.44) 1(4023.02,2542.44) 1(4036.02,2078.44) 1(4041.02,1767.44) 1(4047.02,1589.44) 1(4048.02,1727.44) 1(4048.02,2108.44) 1(4049.16,2392.44) 1(4050.02,1629.44) 1(4051.02,2002.44) 1(4059.27,1223.92) 1(4059.27,1257.92) 1(4059.35,3456) 1(4060.02,1670.44) 1(4063.02,1901.44) 1(4065.02,2190.44) 1(4068.01,1502.66) 1(4072.02,3182.44) 1(4076.43,3573.6) 1(4077.02,1646.44) 1(4078.64,1824.82) 1(4080.5,3221.54) 1(4082.8,653.39) 1(4086.02,2427.44) 1(4087.02,2594.44) 1(4091.27,1223.92) 1(4091.27,1257.92) 1(4092.02,2731.44) 1(4101.02,2918.44) 1(4103.4,1450.79) 1(4104.02,957.44) 1(4104.02,3129.44) 1(4105.02,1347.17) 1(4106.02,1017.44) 1(4106.02,2056.44) 1(4107.02,1981.44) 1(4110.02,1756.44) 1(4111.27,1403.92) 1(4112.02,1914.44) 1(4114.02,1721.44) 1(4116.02,1553.44) 1(4117.65,2605.39) 1(4119.02,2321.44) 1(4120.27,1653.69) 1(4124.02,1861.44) 1(4124.02,2183.44) 1(4131.02,2359.44) 1(4131.43,3573.6) 1(4133.02,2433.44) 1(4135.02,1966.44) 1(4136.02,2581.44) 1(4142.02,2056.44) 1(4149.64,2246.26) 1(4151.02,2938.44) 1(4153.29,599.9) 1(4154.02,1920.44) 1(4155.02,2203.44) 1(4157.02,2314.44) 1(4160.44,3471.39) 1(4161.02,1834.44) 1(4162.65,3226.39) 1(4170.01,1502.66) 1(4170.02,1987.44) 1(4170.37,1616.01) 1(4173.27,1315.92) 1(4175.02,1743.38) 1(4176.65,3499.39) 1(4177.53,1352.66) 1(4178.01,1452.66) 1(4180.01,1402.66) 1(4193.65,2721.39) 1(4197.02,3004.44) 1(4199.65,3584.39) 1(4200.02,2024.44) 1(4200.02,3639.44) 1(4201.02,958.44) 1(4205.02,2602.44) 1(4206.02,1752.44) 1(4206.65,3228.39) 1(4208.02,2137.44) 1(4208.02,2234.44) 1(4209.13,3532.27) 1(4210.02,2321.44) 1(4210.02,2465.44) 1(4210.02,2520.44) 1(4213.02,2169.44) 1(4215.02,1895.44) 1(4216.02,2405.44) 1(4223.22,1982.24) 1(4223.27,642.92) 1(4227.02,1247.44) 1(4230.02,2295.44) 1(4231.02,2489.44) 1(4233.65,3097.39) 1(4234.02,3563.44) 1(4236.02,1767.44) 1(4239.02,3601.44) 1(4241.45,1591.22) 1(4243.02,612.44) 1(4243.02,1823.44) 1(4243.02,2602.44) 1(4244.02,2231.44) 1(4244.02,2917.44) 1(4248.81,3124.55) 1(4249.13,3531.87) 1(4249.74,3203.29) 1(4250.65,3163.39) 1(4253.02,2462.44) 1(4253.7,3006.44) 1(4254.65,2952.39) 1(4257.02,2553.44) 1(4258.02,2142.44) 1(4263.02,2009.41) 1(4263.02,2299.87) 1(4267.97,1697.12) 1(4268.22,2516.24) 1(4268.65,3327.39) 1(4268.91,2373.33) 1(4285.58,2602.32) 1(4285.86,1304.51) 1(4287.01,1352.66) 1(4292.27,1515.92) 1(4293.02,702.44) 1(4293.02,1782.44) 1(4293.02,2172.44) 1(4293.58,2461.88) 1(4293.96,2824.03) 1(4296.27,1700.92) 1(4296.76,1585.61) 1(4297.02,996.44) 1(4298.02,963.44) 1(4298.02,3568.44) 1(4301.91,2370.33) 1(4302.02,2513.44) 1(4303.02,1968.44) 1(4304.02,2550.44) 1(4307.02,1923.44) 1(4308.02,1837.44) 1(4308.02,2583.44) 1(4308.02,4092.44) 1(4310.46,1492.73) 1(4312.02,1875.44) 1(4312.02,2018.44) 1(4313.02,2202.44) 1(4323.27,1234.92) 1(4324.59,3322.44) 1(4326.9,2268.56) 1(4328.02,2237.44) 1(4329.13,3531.87) 1(4330.02,996.44) 1(4331.02,963.44) 1(4332.02,2151.44) 1(4333.02,2632.44) 1(4336.27,1976.92) 1(4343.02,652.44) 1(4343.02,4251.44) 1(4345.65,2677.39) 1(4345.65,2720.39) 1(4348.02,1755.44) 1(4348.02,2446.44) 1(4349.02,2478.44) 1(4350.58,1616.61) 1(4351.91,2307.33) 1(4352.02,2511.44) 1(4352.21,1663.86) 1(4353.02,2192.89) 1(4356.02,2086.44) 1(4357.95,1557.24) 1(4360.02,1115.44) 1(4360.02,1721.44) 1(4363.02,1992.44) 1(4363.02,2022.44) 1(4364.13,3531.87) 1(4367.02,2336.44) 1(4373.02,4312.44) 1(4386.87,1356.84) 1(4386.87,1462.84) 1(4389.02,2317.44) 1(4391.02,2505.44) 1(4393.02,662.44) 1(4393.02,4012.44) 1(4393.02,4462.44) 1(4393.65,3198.39) 1(4395.02,1249.44) 1(4395.53,1316.66) 1(4396.07,1892.59) 1(4397.85,1188.65) 1(4398.53,1281.66) 1(4399.13,3531.87) 1(4409.02,1746.44) 1(4413.02,2195.44) 1(4413.02,4352.44) 1(4416.02,4176.44) 1(4417.02,2290.44) 1(4419.65,3264.39) 1(4419.65,3312.39) 1(4421.02,3064.44) 1(4423.02,3898.44) 1(4425.02,3942.44) 1(4426.02,3977.44) 1(4426.65,3202.39) 1(4429.02,3495.44) 1(4430.02,4525.44) 1(4431.73,1592.84) 1(4432.27,1369.92) 1(4433.02,1817.44) 1(4436.28,4409.39) 1(4438.02,2065.44) 1(4438.28,4209.39) 1(4440.65,3337.39) 1(4443.02,662.44) 1(4453.02,1402.44) 1(4460.02,4059.44) 1(4461.87,1889.84) 1(4463.02,2306.44) 1(4463.85,2638.67) 1(4471.02,2495.44) 1(4492.27,1339.92) 1(4493.02,662.44) 1(4499.02,4053.69) 1(4507.9,1184.29) 1(4508.65,2777.39) 1(4511.02,2385.44) 1(4512.65,2809.39) 1(4517.65,2722.39) 1(4519.02,1784.27) 1(4519.02,2468.44) 1(4523.02,2302.44) 1(4523.02,3907.44) 1(4523.65,2898.39) 1(4523.65,3226.39) 1(4525.65,2865.39) 1(4525.65,3063.39) 1(4529.65,3013.39) 1(4530.65,2980.39) 1(4539.02,4046.34) 1(4543.02,2612.44) 1(4544.65,2939.39) 1(4545.02,2503.44) 1(4548.28,4405.39) 1(4550.02,2405.44) 1(4553.02,4292.44) 1(4553.5,3212.24) 1(4553.9,1184.29) 1(4560.02,2451.44) 1(4562.02,4164.44) 1(4563.02,682.44) 1(4563.02,1362.44) 1(4563.02,1462.44) 1(4564.28,4331.39) 1(4565.02,4237.44) 1(4565.43,4095.03) 1(4573.57,3262.46) 1(4573.65,3301.39) 1(4574.02,1256.64) 1(4585.3,1585.84) 1(4588.3,2081.11) 1(4590.8,652.44) 1(4591.02,1318.44) 1(4593.02,4460.44) 1(4603.02,892.44) 1(4605.02,1284.44) 1(4605.02,2323.44) 1(4608.9,1182.29) 1(4615.3,1585.84) 1(4618.3,2081.11) 1(4619.02,1984.44) 1(4620.02,1681.44) 1(4620.88,2827.15) 1(4622.02,2688.44) 1(4622.2,3126.83) 1(4625.57,3087.46) 1(4627.02,1256.44) 1(4628.02,2496.44) 1(4634.41,2782.15) 1(4646.02,1985.44) 1(4648.3,1585.84) 1(4650.3,1682.84) 1(4651.3,2081.11) 1(4659.1,4296.21) 1(4659.28,4434.39) 1(4660.28,4055.39) 1(4661.28,4248.39) 1(4662.9,1183.29) 1(4663.02,3932.44) 1(4666.02,4193.44) 1(4666.95,3035.08) 1(4667.02,4140.44) 1(4668.02,2665.44) 1(4668.28,4386.39) 1(4671.02,1357.44) 1(4678.3,1585.84) 1(4680.02,4225.44) 1(4681.3,2081.11) 1(4683.02,922.44) 1(4683.02,2292.44) 1(4684.02,968.44) 1(4686.02,4162.44) 1(4694.02,2530.44) 1(4694.28,4346.39) 1(4697.02,4115.44) 1(4697.28,4491.39) 1(4698.33,2828.7) 1(4699.28,4274.39) 1(4701.28,3892.39) 1(4703.02,572.44) 1(4703.02,2501.44) 1(4708.02,874.44) 1(4710.02,2325.44) 1(4713.02,3042.44) 1(4715.02,2587.44) 1(4715.02,3247.44) 1(4716.02,3339.44) 1(4718.02,2646.44) 1(4718.02,2747.44) 1(4718.02,3445.44) 1(4722.71,2974.75) 1(4731.02,154.44) 1(4733.02,772.44) 1(4733.02,1152.44) 1(4733.28,4410.39) 1(4734.02,4157.44) 1(4734.28,3745.39) 1(4734.28,3910.39) 1(4736.02,3303.44) 1(4739.02,220.44) 1(4740.02,2467.44) 1(4743.02,1062.44) 1(4746.02,2416.44) 1(4751.02,840.44) 1(4763.02,792.44) 1(4763.28,4326.39) 1(4767.28,4372.39) 1(4768.02,957.44) 1(4772.28,4005.39) 1(4782.27,834.92) 1(4784.02,197.44) 1(4785.71,4154.13) 1(4786.02,4116.44) 1(4786.28,4298.39) 1(4791.02,2445.44) 1(4792.1,3932.44) 1(4793.02,3858.63) 1(4798.02,1213.44) 1(4800.28,4401.39) 1(4801.06,3971.39) 1(4801.28,4082.39) 1(4801.82,4035.93) 1(4803.02,1122.44) 1(4803.02,2792.44) 1(4806.02,1259.44) 1(4808.12,3887.34) 1(4809.02,1327.44) 1(4810.28,4272.39) 1(4813.02,1152.44) 1(4825.02,1298.44) 1(4837.02,3304.44) 1(4837.45,1595.15) 1(4840.02,3446.44) 1(4840.53,2080.55) 1(4841.02,2897.44) 1(4842.02,2946.44) 1(4845.02,2646.44) 1(4845.02,3344.44) 1(4846.02,2546.44) 1(4847.02,2746.44) 1(4851.02,1337.44) 1(4863.02,2297.44) 1(4868.9,845.39) 1(4871.73,1050.38) 1(4883.02,587.94) 1(4885.87,1455.84) 1(4896.9,846.39) 1(4898.02,755.44) 1(4899.73,1051.38) 1(4900.28,3898.39) 1(4900.28,4213.39) 1(4901.02,1702.44) 1(4913.02,3862.44) 1(4913.02,4332.01) 1(4913.02,4362.44) 1(4923.02,4442.44) 1(4923.25,4054.42) 1(4923.28,4000.39) 1(4928.28,3945.38) 1(4932.61,1842.78) 1(4934.02,1688.84) 1(4939.02,3242.44) 1(4940.02,3146.44) 1(4941.02,3345.44) 1(4942.02,1901.44) 1(4942.02,2646.44) 1(4942.02,2948.44) 1(4943.02,587.94) 1(4943.02,2246.44) 1(4943.02,2882.44) 1(4943.02,4227.08) 1(4943.02,4258.48) 1(4944.02,2007.44) 1(4944.02,2748.44) 1(4945.02,2827.44) 1(4946.02,2702.44) 1(4947.02,2345.44) 1(4948.67,1731.04) 1(4950.02,1778.44) 1(4950.02,3203.44) 1(4951.02,1811.44) 1(4956.76,3923.18) 1(4958.96,1652.44) 1(4961.28,3987.39) 1(4963.55,4097.88) 1(4974.02,1623.44) 1(4979.02,4167.98) 1(4979.02,4199.38) 1(4980.02,729.44) 1(4983.02,512.44) 1(4983.02,552.44) 1(4986.02,3956.44) 1(4988.02,1810.44) 1(4992.02,4286.18) 1(4992.02,4317.58) 1(4994.02,2087.44) 1(4994.02,2389.44) 1(5002.02,1544.44) 1(5009.87,1727.84) 1(5013.02,1142.44) 1(5014.02,2000.44) 1(5022.02,1822.44) 1(5022.02,1970.44) 1(5023.02,4108.88) 1(5023.02,4140.28) 1(5023.17,1639.19) 1(5033.02,761.44) 1(5033.02,812.44) 1(5033.02,1182.44) 1(5037.02,2086.44) 1(5042.28,4016.39) 1(5050.1,1652.27) 1(5058.02,3204.44) 1(5060.02,4060.44) 1(5063.02,1122.44) 1(5063.02,1217.44) 1(5064.02,1987.44) 1(5064.02,2879.44) 1(5066.79,1760.29) 1(5067.02,2648.44) 1(5068.02,2831.44) 1(5069.02,2946.44) 1(5069.02,3144.44) 1(5069.07,3046.39) 1(5070.81,1697.16) 1(5071.02,2720.44) 1(5072.02,1948.44) 1(5074.02,1790.44) 1(5076.02,2122.44) 1(5081.02,2387.44) 1(5082.02,3452.44) 1(5083.02,1182.44) 1(5084.02,2341.44) 1(5093.27,1667.92) 1(5099.02,2096.44) 1(5099.02,2422.44) 1(5101.02,1813.44) 1(5113.02,1732.44) 1(5116.02,1933.44) 1(5120.02,1767.44) 1(5140.02,1545.44) 1(5150.02,2537.44) 1(5156.02,1252.44) 1(5156.02,1366.44) 1(5158.02,585.44) 1(5158.02,3091.44) 1(5165.02,2455.44) 1(5183.87,1625.84) 1(5189.87,1573.84) 1(5190.02,-105.56) 1(5193.02,3022.44) 1(5196.02,2376.44) 1(5196.02,3162.44) 1(5199.02,3202.44) 1(5201.33,1363.98) 1(5201.33,1263.44) 1(5205.02,2459.44) 1(5213.02,752.44) 1(5213.02,802.44) 1(5213.02,842.44) 1(5213.02,892.44) 1(5233.02,4391.44) 1(5240.02,2878.44) 1(5240.76,3120.83) 1(5247.02,3990.44) 1(5250.02,2225.44) 1(5253.02,752.44) 1(5253.02,802.44) 1(5253.02,842.44) 1(5253.02,892.44) 1(5289.02,1867.44) 1(5290.02,3622.44) 1(5292.02,1808.44) 1(5335.02,4241.44) 1(5337.02,1782.44) 1(5341.02,4024.44) 1(5349.02,594.44) 1(5355.02,510.44) 1(5393.02,592.44) 1(5398.02,4024.44) 1(5400.02,4391.44) 1(5404.27,1638.92) 1(5407.02,4506.44) 1(5413.02,1754.44) 1(5414.02,1789.44) 1(5428.02,4138.44) 1(5443.27,1637.92) 1(5466.02,1905.44) 1(5484.27,1596.92) 1(5507.02,1727.44)
  round 40 on Mech21: 1(2872.02,82.44) 1(2872.02,280.19) 1(2872.02,480.05) 1(2972.02,82.44) 1(2972.02,280.19) 1(2972.02,480.05) 1(3128.65,360.39) 1(3128.65,460.39) 1(3228.65,360.39) 1(3228.65,460.39) 1(3278.65,138.39) 1(3278.65,238.39) 1(3328.65,360.39) 1(3328.65,460.39) 1(3378.65,138.39) 1(3378.65,238.39) 1(3428.65,360.39) 1(3428.65,460.39) 1(3478.65,138.39) 1(3478.65,238.39) 1(3522.15,3780.33) 1(3522.15,4508.33) 1(3528.65,360.39) 1(3528.65,460.39) 1(3578.65,138.39) 1(3578.65,238.39) 1(3628.65,360.39) 1(3628.65,460.39) 1(3669.28,1089.39) 1(3669.28,1189.39) 1(3678.65,138.39) 1(3678.65,238.39) 1(3728.65,360.39) 1(3728.65,460.39) 1(3828.65,360.39) 1(3828.65,460.39) 1(3943.65,360.39) 1(3943.65,460.39) 1(4043.65,360.39) 1(4043.65,460.39) 1(4143.65,360.39) 1(4143.65,460.39) 1(4243.65,360.39) 1(4243.65,460.39) 1(4343.65,360.39) 1(4343.65,460.39) 1(4443.65,360.39) 1(4443.65,460.39) 1(4543.65,360.39) 1(4543.65,460.39) 1(4643.65,360.39) 1(4643.65,460.39) 1(4653.65,3780.33) 1(4653.65,4508.33) 1(4789.02,430.44) 1(4789.02,530.44) 1(4911.02,430.44) 1(4911.02,530.44) 1(5235.02,559.44)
